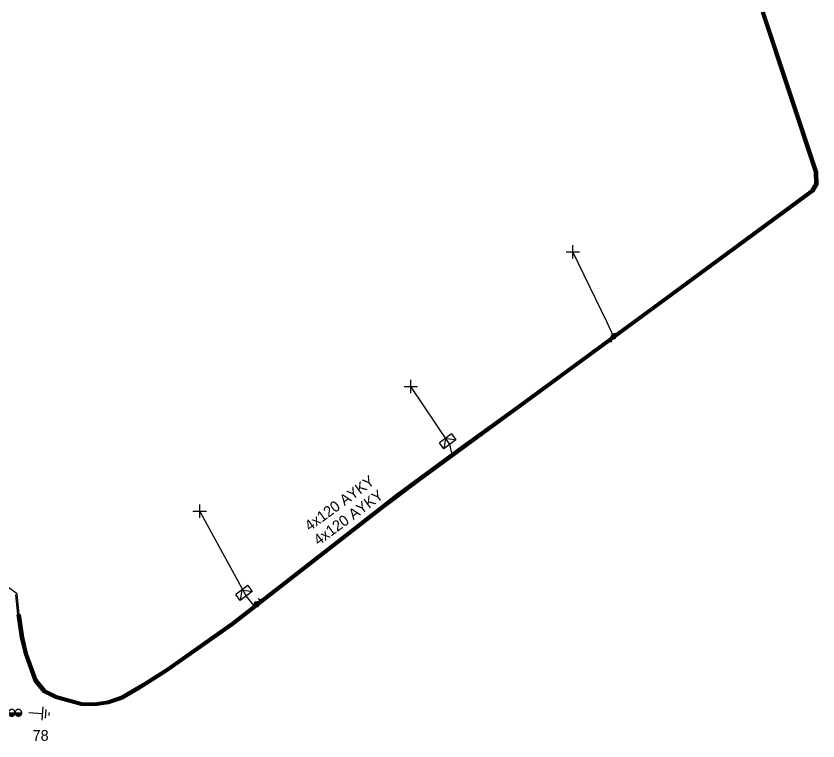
# Model space of a CAD drawing. Extents: x -544780 to -541582, y -1198995 to -1196551.
# Drawn here: x -542533.4 to -542458.8, y -1198053.6 to -1197986.1 of the extents above; entities that cross this region are included whole.
import ezdxf

# ---------------------------------------------------------------- set-up
doc = ezdxf.new("R2010")
doc.units = 0
for name, color, linetype in [('Vrstva 1', 7, 'Continuous'), ('Vrstva 13', 7, 'Continuous'), ('Vrstva 14', 7, 'Continuous'), ('Vrstva 15', 7, 'Continuous'), ('Vrstva 19', 7, 'Continuous'), ('Vrstva 2', 7, 'Continuous'), ('Vrstva 20', 7, 'Continuous'), ('Vrstva 31', 7, 'Continuous'), ('Vrstva 34', 7, 'Continuous'), ('Vrstva 4', 7, 'Continuous'), ('Vrstva 5', 7, 'Continuous'), ('Vrstva 52', 7, 'Continuous'), ('Vrstva 59', 7, 'Continuous'), ('Vrstva 6', 7, 'Continuous'), ('Vrstva 9', 7, 'Continuous')]:
    doc.layers.add(name, color=color, linetype=linetype)

# ---------------------------------------------------------------- blocks, each defined once
blk = doc.blocks.new('NN450')
at = {"layer": 'Vrstva 2'}
for points in [[(0, 0), (0, 0.07), (-0.01, 0.13), (-0.03, 0.19), (-0.05, 0.25), (-0.08, 0.31), (-0.12, 0.37), (-0.16, 0.42), (-0.21, 0.46), (-0.26, 0.51), (-0.31, 0.54), (-0.37, 0.57), (-0.43, 0.59), (-0.5, 0.61), (-0.56, 0.62), (-0.63, 0.62), (-0.69, 0.62), (-0.75, 0.61), (-0.82, 0.59), (-0.88, 0.57), (-0.94, 0.54), (-0.99, 0.51), (-1.04, 0.46), (-1.09, 0.42), (-1.13, 0.37), (-1.17, 0.31), (-1.2, 0.25), (-1.22, 0.19), (-1.24, 0.13), (-1.25, 0.07), (-1.25, 0), (-1.25, -0.07), (-1.24, -0.13), (-1.22, -0.19), (-1.2, -0.25), (-1.17, -0.31), (-1.13, -0.37), (-1.09, -0.42), (-1.04, -0.46), (-0.99, -0.51), (-0.94, -0.54), (-0.88, -0.57), (-0.82, -0.59), (-0.75, -0.61), (-0.69, -0.62), (-0.62, -0.63), (-0.56, -0.62), (-0.5, -0.61), (-0.43, -0.59), (-0.37, -0.57), (-0.31, -0.54), (-0.26, -0.51), (-0.21, -0.46), (-0.16, -0.42), (-0.12, -0.37), (-0.08, -0.31), (-0.05, -0.25), (-0.03, -0.19), (-0.01, -0.13), (0, -0.07), (0, 0)], [(1.25, 0), (1.25, 0.07), (1.24, 0.13), (1.22, 0.19), (1.2, 0.25), (1.17, 0.31), (1.13, 0.37), (1.09, 0.42), (1.04, 0.46), (0.99, 0.51), (0.94, 0.54), (0.88, 0.57), (0.82, 0.59), (0.75, 0.61), (0.69, 0.62), (0.62, 0.62), (0.56, 0.62), (0.5, 0.61), (0.43, 0.59), (0.37, 0.57), (0.31, 0.54), (0.26, 0.51), (0.21, 0.46), (0.16, 0.42), (0.12, 0.37), (0.08, 0.31), (0.05, 0.25), (0.03, 0.19), (0.01, 0.13), (0, 0.07), (0, 0), (0, -0.07), (0.01, -0.13), (0.03, -0.19), (0.05, -0.25), (0.08, -0.31), (0.12, -0.37), (0.16, -0.42), (0.21, -0.46), (0.26, -0.51), (0.31, -0.54), (0.37, -0.57), (0.43, -0.59), (0.5, -0.61), (0.56, -0.62), (0.63, -0.63), (0.69, -0.62), (0.75, -0.61), (0.82, -0.59), (0.88, -0.57), (0.94, -0.54), (0.99, -0.51), (1.04, -0.46), (1.09, -0.42), (1.13, -0.37), (1.17, -0.31), (1.2, -0.25), (1.22, -0.19), (1.24, -0.13), (1.25, -0.07), (1.25, 0)], [(-1.25, 0), (1.25, 0)], [(-1.23, -0.16), (-0.02, -0.16)], [(-1.16, -0.32), (-0.09, -0.32)], [(-1.03, -0.47), (-0.22, -0.47)], [(0.02, -0.16), (1.23, -0.16)], [(0.09, -0.32), (1.16, -0.32)], [(0.22, -0.47), (1.03, -0.47)]]:
    blk.add_lwpolyline(points, dxfattribs=at)
blk = doc.blocks.new('NN880')
at = {"layer": 'Vrstva 4'}
for points in [[(0.001, 0.248), (-0.499, 0)], [(0.001, 0.185), (-0.373, 0)], [(0.001, 0.122), (-0.247, 0)], [(0.001, 0.059), (-0.125, 0)], [(0.501, 0), (0.001, 0.248)], [(0.375, 0), (0.001, 0.185)], [(0.249, 0), (0.001, 0.122)], [(0.127, 0), (0.001, 0.059)], [(-0.566, -0.13), (-0.436, -0.13)], [(-0.499, 0), (0.001, -0.252)], [(-0.499, -0.13), (-0.499, -0.327)], [(-0.373, 0), (0.001, -0.189)], [(-0.247, 0), (0.001, -0.126)], [(-0.125, 0), (0.001, -0.063)], [(0.001, -0.252), (0.501, 0)], [(0.001, -0.189), (0.375, 0)], [(0.001, -0.126), (0.249, 0)], [(0.001, -0.063), (0.127, 0)]]:
    blk.add_lwpolyline(points, dxfattribs=at)
blk = doc.blocks.new('NN800')
at = {"layer": 'Vrstva 1'}
for points in [[(-0.442, 0.442), (0.442, -0.442)], [(-0.442, -0.442), (0.442, 0.442)]]:
    blk.add_lwpolyline(points, dxfattribs=at)
blk = doc.blocks.new('NN630')
at = {"layer": 'Vrstva 9'}
for points in [[(-0.003, -0.7), (-0.703, 0)], [(-0.703, -0.7), (-0.703, 0), (0.697, 0), (0.697, -0.7)], [(-0.703, -0.7), (0.697, -0.7)], [(-0.003, -0.7), (0.697, 0)]]:
    blk.add_lwpolyline(points, dxfattribs=at)
blk = doc.blocks.new('NN810')
at = {"layer": 'Vrstva 14'}
for points in [[(0.004, -0.64), (0.004, -1.89)], [(0.629, -1.89), (-0.621, -1.89)], [(0.388, -2.2), (-0.399, -2.2)], [(0.004, -2.515), (-0.124, -2.515)], [(0.137, -2.515), (0.004, -2.515)]]:
    blk.add_lwpolyline(points, dxfattribs=at)

msp = doc.modelspace()

# ---------------------------------------------------------------- linework, layer by layer
at = {"layer": 'Vrstva 20'}
for points in [[(-542463.818, -1197985.736), (-542458.87, -1198000.624), (-542458.818, -1198001.816), (-542459.234, -1198002.506), (-542479.71, -1198017.565), (-542484.48, -1198021.06), (-542495.868, -1198029.409), (-542499.241, -1198031.943), (-542506.208, -1198037.367), (-542513.222, -1198042.838), (-542519.351, -1198047.142), (-542522.005, -1198048.8), (-542523.492, -1198049.668), (-542524.788, -1198050.106), (-542526.051, -1198050.29), (-542527.33, -1198050.27), (-542529.72, -1198049.612), (-542530.839, -1198049.051), (-542531.694, -1198048), (-542532.604, -1198045.48), (-542532.958, -1198043.956), (-542533.288, -1198041.842), (-542533.15, -1198041.82), (-542532.82, -1198043.93), (-542532.47, -1198045.44), (-542531.57, -1198047.93), (-542530.75, -1198048.94), (-542529.67, -1198049.48), (-542527.31, -1198050.13), (-542526.025, -1198050.135), (-542524.821, -1198049.969), (-542523.55, -1198049.54), (-542521.305, -1198048.222), (-542519.26, -1198046.9), (-542513.152, -1198042.609), (-542512.098, -1198041.797), (-542501.006, -1198033.122), (-542497.729, -1198030.569), (-542492.336, -1198026.624), (-542479.075, -1198016.912), (-542461.939, -1198004.307), (-542459.34, -1198002.41), (-542458.96, -1198001.78), (-542459.01, -1198000.65), (-542463.951, -1197985.78)], [(-542463.951, -1197985.78), (-542459.01, -1198000.65), (-542458.96, -1198001.78), (-542459.34, -1198002.41), (-542492.336, -1198026.624), (-542497.74, -1198030.581), (-542499.879, -1198032.244), (-542506.865, -1198037.704), (-542512.957, -1198042.456), (-542513.426, -1198042.804), (-542519.26, -1198046.9), (-542521.305, -1198048.222), (-542523.55, -1198049.54), (-542524.821, -1198049.969), (-542526.025, -1198050.135), (-542527.31, -1198050.13), (-542529.67, -1198049.48), (-542530.75, -1198048.94), (-542531.57, -1198047.93), (-542532.47, -1198045.44), (-542532.82, -1198043.93), (-542533.15, -1198041.82), (-542532.997, -1198041.797), (-542532.682, -1198043.903), (-542532.336, -1198045.4), (-542531.446, -1198047.86), (-542530.66, -1198048.828), (-542529.62, -1198049.349), (-542527.29, -1198049.99), (-542526.07, -1198050.01), (-542524.853, -1198049.833), (-542523.608, -1198049.412), (-542521.423, -1198048.132), (-542519.338, -1198046.784), (-542513.276, -1198042.526), (-542502.816, -1198034.36), (-542497.964, -1198030.598), (-542491.997, -1198026.192), (-542486.893, -1198022.487), (-542474.213, -1198013.197), (-542459.445, -1198002.314), (-542459.102, -1198001.744), (-542459.149, -1198000.676), (-542464.083, -1197985.824)]]:
    msp.add_lwpolyline(points, dxfattribs=at)
at = {"layer": 'Vrstva 5'}
for points in [[(-542464.017, -1197985.802), (-542459.079, -1198000.663), (-542459.031, -1198001.762), (-542459.392, -1198002.362), (-542469.406, -1198009.742), (-542474.172, -1198013.253), (-542477.815, -1198015.922), (-542486.852, -1198022.543), (-542492.82, -1198026.92), (-542497.922, -1198030.654), (-542502.773, -1198034.415), (-542511.03, -1198040.87), (-542513.311, -1198042.653), (-542519.299, -1198046.842), (-542521.406, -1198048.211), (-542523.579, -1198049.476), (-542524.837, -1198049.901), (-542526.065, -1198050.08), (-542527.3, -1198050.06), (-542529.645, -1198049.415), (-542530.705, -1198048.884), (-542531.508, -1198047.895), (-542532.403, -1198045.42), (-542532.751, -1198043.916), (-542533.081, -1198041.809), (-542533.263, -1198039.881), (-542534.056, -1198039.321)], [(-542463.884, -1197985.758), (-542458.94, -1198000.637), (-542458.889, -1198001.798), (-542459.287, -1198002.458), (-542474.089, -1198013.366), (-542486.769, -1198022.656), (-542497.838, -1198030.766), (-542502.687, -1198034.525), (-542513.228, -1198042.766), (-542519.221, -1198046.958), (-542521.333, -1198048.33), (-542523.521, -1198049.604), (-542524.804, -1198050.038), (-542526.056, -1198050.22), (-542527.32, -1198050.2), (-542529.695, -1198049.546), (-542530.795, -1198048.996), (-542531.632, -1198047.965), (-542532.537, -1198045.46), (-542532.889, -1198043.943), (-542533.219, -1198041.831), (-542533.397, -1198039.959)]]:
    msp.add_lwpolyline(points, dxfattribs=at)
at = {"layer": 'Vrstva 52'}
for points in [[(-542477.814, -1198015.922), (-542478.407, -1198014.659)], [(-542492.82, -1198026.92), (-542493.04, -1198025.98)], [(-542511.03, -1198040.87), (-542511.23, -1198040.99), (-542511.98, -1198040.08)]]:
    msp.add_lwpolyline(points, dxfattribs=at)
at = {"layer": 'Vrstva 59'}
for points in [[(-542478.407, -1198014.659), (-542481.608, -1198008.079)], [(-542493.04, -1198025.98), (-542496.679, -1198020.59)], [(-542511.98, -1198040.08), (-542516.305, -1198032.203)]]:
    msp.add_lwpolyline(points, dxfattribs=at)

# ---------------------------------------------------------------- block references
at = {"layer": 'Vrstva 13', "xscale": 0.5, "yscale": 0.5, "rotation": 0.4468972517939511}
msp.add_blockref('NN450', (-542533.472, -1198050.951), dxfattribs=at)
at = {"layer": 'Vrstva 15', "rotation": 85.79227226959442}
msp.add_blockref('NN810', (-542532.828, -1198050.882), dxfattribs=at)
at = {"layer": 'Vrstva 19'}
for p, rotation in [((-542477.814, -1198015.922), 36.38554155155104), ((-542511.03, -1198040.87), -141.98375832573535)]:
    msp.add_blockref('NN880', p, dxfattribs=dict(at, rotation=rotation))
at = {"layer": 'Vrstva 31'}
for p, rotation in [((-542493.04, -1198025.98), -143.3764971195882), ((-542511.98, -1198040.08), -143.41027498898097)]:
    msp.add_blockref('NN630', p, dxfattribs=dict(at, rotation=rotation))
at = {"layer": 'Vrstva 34', "rotation": 45}
for p in [(-542481.608, -1198008.079), (-542496.679, -1198020.59), (-542516.305, -1198032.203)]:
    msp.add_blockref('NN800', p, dxfattribs=at)

# ---------------------------------------------------------------- texts
at = {"layer": 'Vrstva 14'}
msp.add_text('78', height=1, rotation=0.447, dxfattribs=at).set_placement((-542531.835, -1198053.563))
at = {"layer": 'Vrstva 6'}
for rotation, p in [(36.23, (-542506.077, -1198034.098)), (36.229, (-542505.251, -1198035.417))]:
    msp.add_text('4x120 AYKY', height=1, rotation=rotation, dxfattribs=at).set_placement(p)

doc.saveas('drawing.dxf')
